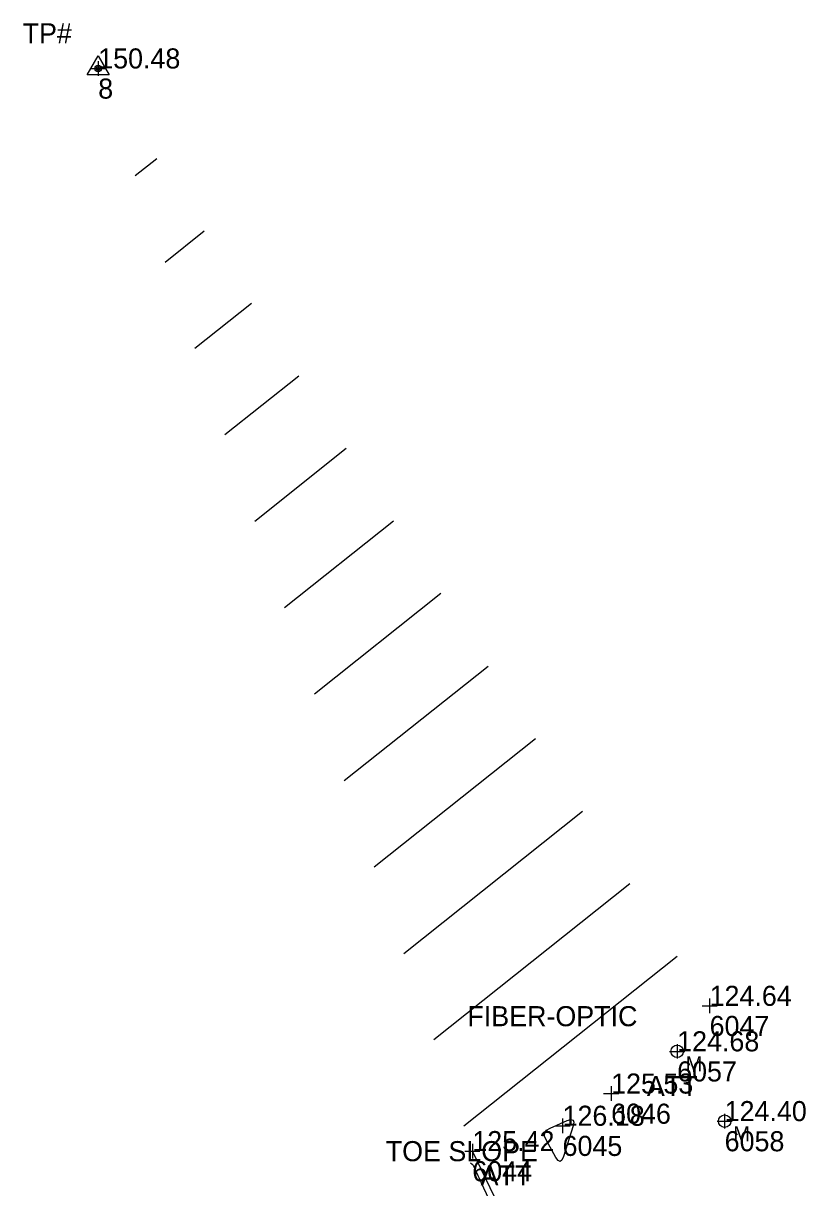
# Model space of a CAD drawing. Extents: x 13482745 to 13483091, y 311698 to 312158.
# Drawn here: x 13482811.5 to 13482936.2, y 311972.3 to 312157.8 of the extents above; entities that cross this region are included whole.
import ezdxf

# ---------------------------------------------------------------- set-up
doc = ezdxf.new("R2010")
doc.units = 0
for name, color, linetype in [('V-PROP-IDEN', 7, 'Continuous'), ('V-SITE-FEAT', 7, 'Continuous'), ('V-SITE-IDEN', 7, 'Continuous'), ('V-SITE-SPOT', 7, 'Continuous'), ('V-SURV-DATA', 7, 'Continuous'), ('V-SURV-PNTS', 7, 'Continuous'), ('V-SURV-SPOT', 7, 'Continuous'), ('V-TOPO-DRAN-SPOT', 7, 'Continuous'), ('V-TOPO-DRAN-TOE', 7, 'Continuous'), ('V-TOPO-LINE-IDEN', 7, 'Continuous'), ('V-TOPO-MAJR', 7, 'Continuous'), ('V-TOPO-MINR', 7, 'Continuous'), ('V-TOPO-SPOT', 7, 'Continuous')]:
    doc.layers.add(name, color=color, linetype=linetype)

msp = doc.modelspace()

# ---------------------------------------------------------------- linework, layer by layer
at = {"layer": 'V-SITE-FEAT'}
for centre in [(13482915.67, 311994.03), (13482923.24, 311982.91)]:
    msp.add_circle(centre, 1, dxfattribs=at)
at = {"layer": 'V-SITE-SPOT'}
for p, q in [((13482915.67, 311995.19), (13482915.67, 311992.87)), ((13482914.47, 311994.03), (13482916.87, 311994.03)), ((13482923.24, 311984.07), (13482923.24, 311981.75)), ((13482922.04, 311982.91), (13482924.44, 311982.91))]:
    msp.add_line(p, q, dxfattribs=at)
at = {"layer": 'V-SURV-DATA'}
msp.add_lwpolyline([(13482823.41, 312152.6), (13482825.17, 312149.56), (13482821.65, 312149.56)], close=True, dxfattribs=at)
msp.add_lwpolyline([(13482823.41, 312152.6), (13482825.17, 312149.56), (13482821.65, 312149.56)], close=True, dxfattribs=at)
for radius in [0.508, 0.508, 0.305, 0.305, 0.102, 0.102]:
    msp.add_circle((13482823.41, 312150.58), radius, dxfattribs=at)
at = {"layer": 'V-SURV-SPOT'}
for p, q in [((13482823.41, 312151.74), (13482823.41, 312149.42)), ((13482823.41, 312151.74), (13482823.41, 312149.42)), ((13482822.21, 312150.58), (13482824.61, 312150.58)), ((13482822.21, 312150.58), (13482824.61, 312150.58))]:
    msp.add_line(p, q, dxfattribs=at)
at = {"layer": 'V-TOPO-DRAN-SPOT'}
for p, q in [((13482883.03, 311979.29), (13482883.03, 311976.97)), ((13482881.83, 311978.13), (13482884.23, 311978.13))]:
    msp.add_line(p, q, dxfattribs=at)
at = {"layer": 'V-TOPO-DRAN-TOE'}
msp.add_lwpolyline([(13482905.49, 311931.6), (13482883.03, 311978.13)], dxfattribs=at)
at = {"layer": 'V-TOPO-MAJR'}
for points in [[(13482824.55, 312147.28), (13482825.22, 312147.81)], [(13482862.92, 312090.04), (13482848.35, 312078.45)], [(13482872.14, 312009.62), (13482900.61, 312032.26)]]:
    msp.add_lwpolyline(points, dxfattribs=at)
at = {"layer": 'V-TOPO-MINR'}
for points in [[(13482829.31, 312133.51), (13482832.76, 312136.25)], [(13482834.07, 312119.75), (13482840.3, 312124.7)], [(13482847.84, 312113.14), (13482838.83, 312105.98)], [(13482855.38, 312101.59), (13482843.59, 312092.21)], [(13482870.46, 312078.48), (13482853.1, 312064.68)], [(13482877.99, 312066.93), (13482857.86, 312050.92)], [(13482862.62, 312037.15), (13482885.53, 312055.37)], [(13482893.07, 312043.82), (13482867.38, 312023.39)], [(13482908.15, 312020.71), (13482876.9, 311995.86)], [(13482915.69, 312009.15), (13482881.66, 311982.09)], [(13482882.74, 311976.25), (13482883.01, 311976.07), (13482883.05, 311976.03), (13482883.08, 311976), (13482883.12, 311975.95), (13482883.14, 311975.91), (13482883.92, 311974.26), (13482884.05, 311973.96), (13482884.19, 311973.67), (13482884.33, 311973.38), (13482884.46, 311973.09), (13482904.02, 311931.26)]]:
    msp.add_lwpolyline(points, dxfattribs=at)
msp.add_lwpolyline([(13482894.55, 311980.53), (13482894.57, 311981.05), (13482894.87, 311981.47), (13482895.42, 311981.81), (13482898.16, 311982.99), (13482898.73, 311983.16), (13482899.08, 311983.07), (13482899.2, 311982.74), (13482899.09, 311982.15), (13482897.56, 311977.27), (13482897.31, 311976.7), (13482897.02, 311976.49), (13482896.7, 311976.64), (13482896.33, 311977.14), (13482894.78, 311979.92)], close=True, dxfattribs=at)
at = {"layer": 'V-TOPO-SPOT'}
for p, q in [((13482919.64, 312001.27), (13482922.04, 312001.27)), ((13482920.84, 312002.43), (13482920.84, 312000.11)), ((13482905.15, 311988.46), (13482905.15, 311986.14)), ((13482903.95, 311987.3), (13482906.35, 311987.3)), ((13482896.21, 311982.17), (13482898.61, 311982.17)), ((13482897.41, 311983.33), (13482897.41, 311981.01))]:
    msp.add_line(p, q, dxfattribs=at)

# ---------------------------------------------------------------- texts
at = {"layer": 'V-PROP-IDEN'}
msp.add_text('TP#', height=3.2, dxfattribs=at).set_placement((13482811.37, 312154.58))
msp.add_text('TP#', height=3.2, dxfattribs=at).set_placement((13482811.37, 312154.58))
at = {"layer": 'V-SITE-FEAT'}
for p in [(13482917.03, 311990.83), (13482924.6, 311979.71)]:
    msp.add_text('M', height=2.4, rotation=360, dxfattribs=at).set_placement(p)
at = {"layer": 'V-SITE-IDEN'}
for s, p in [('FIBER-OPTIC', (13482882.24, 311998.03)), ('ATT', (13482910.85, 311986.91)), ('ATT', (13482884.35, 311972.68))]:
    msp.add_text(s, height=3.2, dxfattribs=at).set_placement(p)
at = {"layer": 'V-SITE-SPOT'}
for s, p in [('124.68', (13482915.67, 311994.03)), ('124.40', (13482923.24, 311982.91))]:
    msp.add_text(s, height=3.2, dxfattribs=at).set_placement(p)
at = {"layer": 'V-SURV-PNTS'}
for s, p in [('8', (13482823.41, 312145.78)), ('8', (13482823.41, 312145.78)), ('6047', (13482920.84, 311996.47)), ('6057', (13482915.67, 311989.23)), ('6046', (13482905.15, 311982.5)), ('6045', (13482897.41, 311977.37)), ('6058', (13482923.24, 311978.11)), ('6044', (13482883.03, 311973.33))]:
    msp.add_text(s, height=3.2, dxfattribs=at).set_placement(p)
at = {"layer": 'V-SURV-SPOT'}
msp.add_text('150.48', height=3.2, dxfattribs=at).set_placement((13482823.41, 312150.58))
msp.add_text('150.48', height=3.2, dxfattribs=at).set_placement((13482823.41, 312150.58))
at = {"layer": 'V-TOPO-DRAN-SPOT'}
msp.add_text('125.42', height=3.2, dxfattribs=at).set_placement((13482883.03, 311978.13))
at = {"layer": 'V-TOPO-LINE-IDEN'}
msp.add_text('TOE SLOPE', height=3.2, dxfattribs=at).set_placement((13482869.23, 311976.53))
at = {"layer": 'V-TOPO-SPOT'}
for s, p in [('124.64', (13482920.84, 312001.27)), ('125.53', (13482905.15, 311987.3)), ('126.18', (13482897.41, 311982.17))]:
    msp.add_text(s, height=3.2, dxfattribs=at).set_placement(p)

doc.saveas('drawing.dxf')
